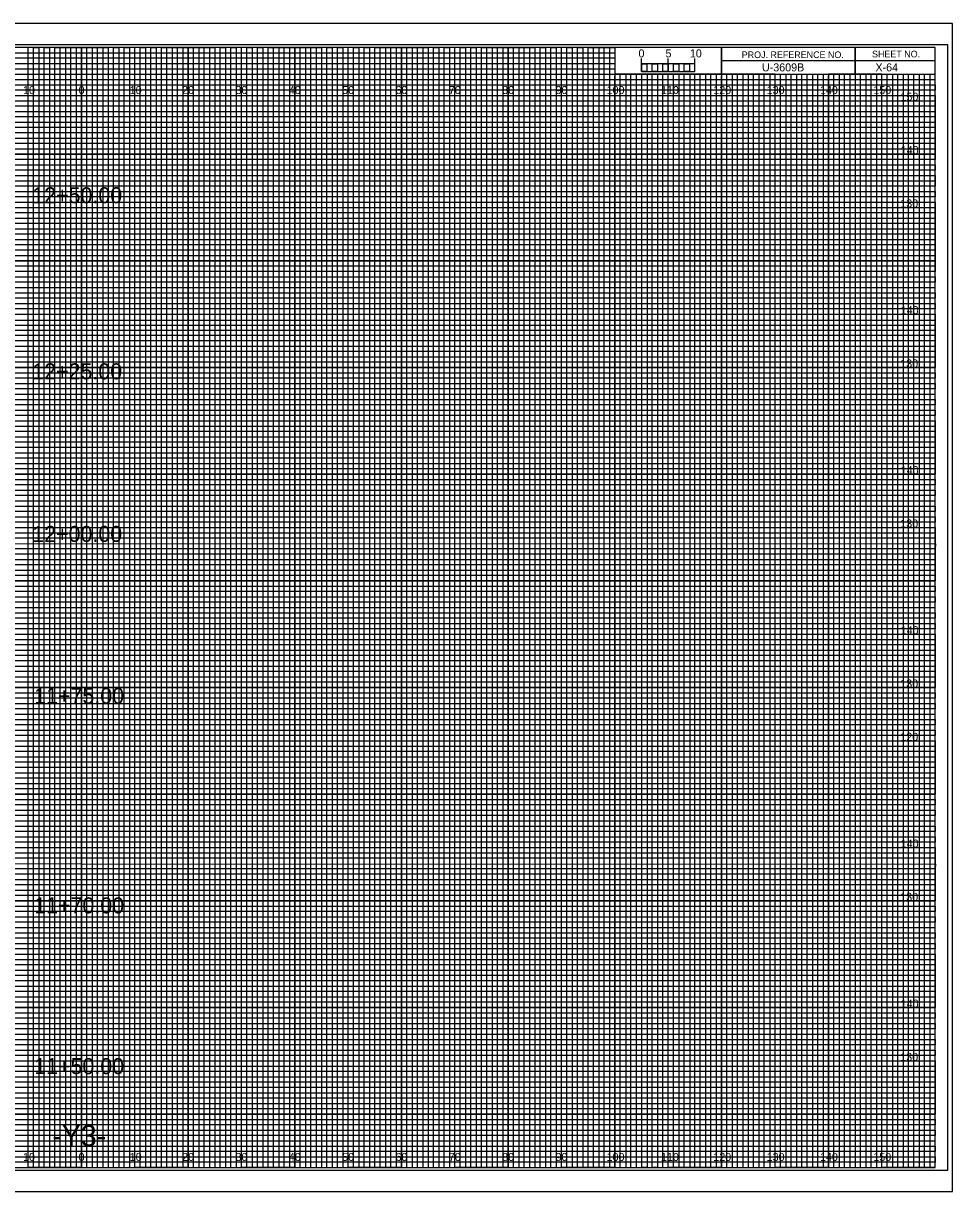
# Model space of a CAD drawing. Extents: x -13 to 323, y -5 to 215.
# Drawn here: x 149.1 to 323.3, y -4.5 to 214.5 of the extents above; entities that cross this region are included whole.
import ezdxf

# ---------------------------------------------------------------- set-up
doc = ezdxf.new("R2010")
doc.units = 0
for name, color, linetype in [('Exist CMT Pavement', 7, 'Continuous'), ('Exist Cross Section Cell', 7, 'Continuous'), ('Exist XS Center Line Elevation Label', 7, 'Continuous'), ('Exist XS Ground Line', 7, 'Continuous'), ('Prop CMT Pvmt Course 1 Wedge', 7, 'Continuous'), ('Prop CMT Pvmt Course 2', 7, 'Continuous'), ('Prop CMT Pvmt Course 2 Wedge', 7, 'Continuous'), ('Prop CMT Pvmt Course 3', 7, 'Continuous'), ('Prop CMT Pvmt Course 3 Wedge', 7, 'Continuous'), ('Prop CMT Pvmt Surface', 7, 'Continuous'), ('Prop CMT Pvmt Wedge Surface 1', 7, 'Continuous'), ('Prop CMT Pvmt Wedge Surface 2', 7, 'Continuous'), ('Prop CMT Shld Paved Course 1', 7, 'Continuous'), ('Prop CMT Shld Paved Course 2', 7, 'Continuous'), ('Prop CMT Shld Paved Course 3', 7, 'Continuous'), ('Prop CMT Subgrade Earthwork', 7, 'Continuous'), ('Scratch_Level_0', 7, 'Continuous')]:
    doc.layers.add(name, color=color, linetype=linetype)

msp = doc.modelspace()

# ---------------------------------------------------------------- linework, layer by layer
at = {"layer": 'Exist XS Center Line Elevation Label'}
for points in [[(145, 0), (155, 0), (155, 210), (165, 210), (165, 0), (175, 0), (175, 210), (185, 210), (185, 0), (195, 0), (195, 210), (205, 210), (205, 0), (215, 0), (215, 210), (225, 210), (225, 0), (235, 0), (235, 210), (245, 210), (245, 0), (255, 0), (255, 210), (259.93, 210), (260, 210), (260, 205), (264.99, 205), (264.99, 0), (275, 0), (275, 205), (285, 205), (285, 0), (295, 0), (295, 205), (305, 205), (305, 0), (315, 0), (315, 205)], [(0, 205), (275, 205)], [(0, 185), (320, 185), (320, 195), (0, 195)], [(0, 165), (320, 165), (320, 175), (0, 175)], [(0, 145), (320, 145), (320, 155), (0, 155)], [(0, 125), (320, 125), (320, 135), (0, 135)], [(0, 105), (320, 105), (320, 115), (0, 115)], [(0, 85), (320, 85), (320, 95), (0, 95)], [(0, 65), (320, 65), (320, 75), (0, 75)], [(0, 45), (320, 45), (320, 55), (0, 55)], [(0, 25), (320, 25), (320, 35), (0, 35)], [(0, 5), (320, 5), (320, 15), (0, 15)]]:
    msp.add_lwpolyline(points, dxfattribs=at)
at = {"layer": 'Exist XS Ground Line'}
for p, q in [((150, 210), (140, 210)), ((150, 0), (150, 210)), ((170, 210), (160, 210)), ((160, 210), (160, 0)), ((170, 0), (170, 210)), ((190, 210), (180, 210)), ((180, 210), (180, 0)), ((190, 0), (190, 210)), ((210, 210), (200, 210)), ((200, 210), (200, 0)), ((210, 0), (210, 210)), ((230, 210), (220, 210)), ((220, 210), (220, 0)), ((230, 0), (230, 210)), ((250, 210), (240, 210)), ((240, 210), (240, 0)), ((250, 0), (250, 210)), ((260, 210), (260, 0)), ((270, 0), (270, 205)), ((290, 205), (280, 205)), ((280, 205), (280, 0)), ((290, 0), (290, 205)), ((310, 205), (300, 205)), ((300, 205), (300, 0)), ((310, 0), (310, 205)), ((160, 0), (150, 0)), ((180, 0), (170, 0)), ((200, 0), (190, 0)), ((220, 0), (210, 0)), ((240, 0), (230, 0)), ((260, 0), (250, 0)), ((280, 0), (270, 0)), ((300, 0), (290, 0)), ((320, 0), (310, 0)), ((320, 0), (320, 0))]:
    msp.add_line(p, q, dxfattribs=at)
for points in [[(0, 200), (320, 200), (320, 190), (0, 190)], [(0, 180), (320, 180), (320, 170), (0, 170)], [(0, 160), (320, 160), (320, 150), (0, 150)], [(0, 140), (320, 140), (320, 130), (0, 130)], [(0, 120), (320, 120), (320, 110), (0, 110)], [(0, 100), (320, 100), (320, 90), (0, 90)], [(0, 80), (320, 80), (320, 70), (0, 70)], [(0, 60), (320, 60), (320, 50), (0, 50)], [(0, 40), (320, 40), (320, 30), (0, 30)], [(0, 20), (320, 20), (320, 10), (0, 10)]]:
    msp.add_lwpolyline(points, dxfattribs=at)
at = {"layer": 'Prop CMT Pvmt Course 1 Wedge'}
for p, q in [((323.3, 214.5), (-13.4, 214.5)), ((-13.4, -4.5), (323.3, -4.5))]:
    msp.add_line(p, q, dxfattribs=at)
at = {"layer": 'Prop CMT Pvmt Course 2'}
msp.add_lwpolyline([(-13.4, -4.5), (323.3, -4.5), (323.3, 214.5), (-13.4, 214.5)], close=True, dxfattribs=at)
at = {"layer": 'Prop CMT Pvmt Course 3'}
msp.add_lwpolyline([(-10.8, -0.5), (322.4, -0.5), (322.4, 210.5), (-10.8, 210.5)], close=True, dxfattribs=at)
at = {"layer": 'Prop CMT Shld Paved Course 1'}
for p, q in [((305, 210), (305, 205)), ((305, 205), (305, 210)), ((280, 207.5), (280, 205)), ((320, 207.49), (280, 207.49)), ((280, 205), (320, 205))]:
    msp.add_line(p, q, dxfattribs=at)
for points in [[(320, 210), (0, 210), (0, 0), (320, 0)], [(280, 210), (260, 210), (260, 205.03), (280, 205.03)], [(320, 210), (280, 210), (280, 205), (320, 205)]]:
    msp.add_lwpolyline(points, close=True, dxfattribs=at)
at = {"layer": 'Prop CMT Shld Paved Course 2'}
for p, q in [((267, 205), (266.01, 205)), ((266.01, 205), (266.01, 0)), ((267, 0), (267, 205)), ((269, 205), (268, 205)), ((268, 205), (268, 0)), ((269, 0), (269, 205)), ((266.01, 0), (265, 0)), ((268, 0), (267, 0))]:
    msp.add_line(p, q, dxfattribs=at)
for points in [[(150, 0), (151, 0), (151, 210), (152, 210), (152, 0)], [(152, 0), (153, 0), (153, 210), (154, 210), (154, 0)], [(155, 0), (156, 0), (156, 210), (157, 210), (157, 0)], [(157, 0), (158, 0), (158, 210), (159, 210), (159, 0)], [(160, 0), (161, 0), (161, 210), (162, 210), (162, 0)], [(162, 0), (163, 0), (163, 210), (164, 210), (164, 0)], [(165, 0), (166, 0), (166, 210), (167, 210), (167, 0)], [(167, 0), (168, 0), (168, 210), (169, 210), (169, 0)], [(170, 0), (171, 0), (171, 210), (172, 210), (172, 0)], [(172, 0), (173, 0), (173, 210), (174, 210), (174, 0)], [(175, 0), (176, 0), (176, 210), (177, 210), (177, 0)], [(177, 0), (178, 0), (178, 210), (179, 210), (179, 0)], [(180, 0), (181, 0), (181, 210), (182, 210), (182, 0)], [(182, 0), (183, 0), (183, 210), (184, 210), (184, 0)], [(185, 0), (186, 0), (186, 210), (187, 210), (187, 0)], [(187, 0), (188, 0), (188, 210), (189, 210), (189, 0)], [(190, 0), (191, 0), (191, 210), (192, 210), (192, 0)], [(192, 0), (193, 0), (193, 210), (194, 210), (194, 0)], [(195, 0), (196, 0), (196, 210), (197, 210), (197, 0)], [(197, 0), (198, 0), (198, 210), (199, 210), (199, 0)], [(200, 0), (201, 0), (201, 210), (202, 210), (202, 0)], [(202, 0), (203, 0), (203, 210), (204, 210), (204, 0)], [(205, 0), (206, 0), (206, 210), (207, 210), (207, 0)], [(207, 0), (208, 0), (208, 210), (209, 210), (209, 0)], [(210, 0), (211, 0), (211, 210), (212, 210), (212, 0)], [(212, 0), (213, 0), (213, 210), (214, 210), (214, 0)], [(215, 0), (216, 0), (216, 210), (217, 210), (217, 0)], [(217, 0), (218, 0), (218, 210), (219, 210), (219, 0)], [(220, 0), (221, 0), (221, 210), (222, 210), (222, 0)], [(222, 0), (223, 0), (223, 210), (224, 210), (224, 0)], [(225, 0), (226, 0), (226, 210), (227, 210), (227, 0)], [(227, 0), (228, 0), (228, 210), (229, 210), (229, 0)], [(230, 0), (231, 0), (231, 210), (232, 210), (232, 0)], [(232, 0), (233, 0), (233, 210), (234, 210), (234, 0)], [(235, 0), (236, 0), (236, 210), (237, 210), (237, 0)], [(237, 0), (238, 0), (238, 210), (239, 210), (239, 0)], [(240, 0), (241, 0), (241, 210), (242, 210), (242, 0)], [(242, 0), (243, 0), (243, 210), (244, 210), (244, 0)], [(245, 0), (246, 0), (246, 210), (247, 210), (247, 0)], [(247, 0), (248, 0), (248, 210), (249, 210), (249, 0)], [(250, 0), (251, 0), (251, 210), (252, 210), (252, 0)], [(252, 0), (253, 0), (253, 210), (254, 210), (254, 0)], [(255, 0), (256, 0), (256, 210), (257, 210), (257, 0)], [(257, 0), (258, 0), (258, 210), (259, 210), (259, 0)], [(260, 0), (261, 0), (261, 205), (262.02, 205), (262.02, 0)], [(262, 0), (263, 0), (263, 205), (263.99, 205), (263.99, 0)], [(270, 0), (270.98, 0), (270.98, 205), (272, 205), (272, 0)], [(272, 0), (273, 0), (273, 205), (274.05, 205), (274.05, 0)], [(275, 0), (276, 0), (276, 205), (277, 205), (277, 0)], [(277, 0), (278, 0), (278, 205), (279, 205), (279, 0)], [(280, 0), (281, 0), (281, 205), (282, 205), (282, 0)], [(282, 0), (283, 0), (283, 205), (284, 205), (284, 0)], [(285, 0), (286, 0), (286, 205), (287, 205), (287, 0)], [(287, 0), (288, 0), (288, 205), (289, 205), (289, 0)], [(290, 0), (291, 0), (291, 205), (292, 205), (292, 0)], [(292, 0), (293, 0), (293, 205), (294, 205), (294, 0)], [(295, 0), (296, 0), (296, 205), (297, 205), (297, 0)], [(297, 0), (298, 0), (298, 205), (299, 205), (299, 0)], [(300, 0), (301, 0), (301, 205), (302, 205), (302, 0)], [(302, 0), (303, 0), (303, 205), (304, 205), (304, 0)], [(305, 0), (306, 0), (306, 205), (307, 205), (307, 0)], [(307, 0), (308, 0), (308, 205), (309, 205), (309, 0)], [(310, 0), (311, 0), (311, 205), (312, 205), (312, 0)], [(312, 0), (313, 0), (313, 205), (314, 205), (314, 0)], [(315, 0), (316, 0), (316, 205), (317, 205), (317, 0)], [(317, 0), (318, 0), (318, 205), (319, 205), (319, 0)]]:
    msp.add_lwpolyline(points, dxfattribs=at)
at = {"layer": 'Prop CMT Shld Paved Course 3'}
for p, q in [((265, 205.49), (265, 207.9)), ((265, 206.9), (265, 207.9)), ((270, 205.49), (270, 207.9)), ((275, 205.49), (275, 207.9)), ((275, 206.9), (275, 207.9))]:
    msp.add_line(p, q, dxfattribs=at)
for points in [[(275, 206.9), (265, 206.9), (265, 205.49), (275, 205.49)], [(265, 206.9), (266, 206.9), (266, 205.49), (265, 205.49)], [(267, 206.9), (268, 206.9), (268, 205.49), (267, 205.49)], [(269, 206.9), (270, 206.9), (270, 205.49), (269, 205.49)], [(271, 206.9), (272, 206.9), (272, 205.49), (271, 205.49)], [(273, 206.9), (274, 206.9), (274, 205.49), (273, 205.49)]]:
    msp.add_lwpolyline(points, close=True, dxfattribs=at)
at = {"layer": 'Prop CMT Subgrade Earthwork'}
for p, q in [((150, 0), (150, 210)), ((160, 0), (160, 210)), ((170, 0), (170, 210)), ((180, 0), (180, 210)), ((190, 0), (190, 210)), ((200, 0), (200, 210)), ((210, 0), (210, 210)), ((220, 0), (220, 210)), ((230, 0), (230, 210)), ((240, 0), (240, 210)), ((250, 0), (250, 210)), ((260, 0), (260, 204.69)), ((270, 0), (270, 204.69)), ((280, 0), (280, 204.69)), ((290, 0), (290, 204.69)), ((300, 0), (300, 204.69)), ((310, 0), (310, 204.69)), ((0, 200), (320, 200)), ((0, 190), (320, 190)), ((0, 180), (320, 180)), ((0, 170), (320, 170)), ((0, 160), (320, 160)), ((0, 150), (320, 150)), ((0, 140), (320, 140)), ((0, 130), (320, 130)), ((0, 120), (320, 120)), ((0, 110), (320, 110)), ((0, 100), (320, 100)), ((0, 90), (320, 90)), ((0, 80), (320, 80)), ((0, 70), (320, 70)), ((0, 60), (320, 60)), ((0, 50), (320, 50)), ((0, 40), (320, 40)), ((0, 30), (320, 30)), ((0, 20), (320, 20)), ((0, 10), (320, 10))]:
    msp.add_line(p, q, dxfattribs=at)
at = {"layer": 'Scratch_Level_0'}
for p, q in [((0, 209), (260, 209)), ((260, 209), (260, 207.98)), ((260, 207.98), (0, 207.98)), ((0, 207), (260, 207)), ((260, 205.89), (0, 205.89)), ((260, 207), (260, 205.89)), ((0, 204), (320, 204))]:
    msp.add_line(p, q, dxfattribs=at)
for points in [[(0, 203), (270, 203), (320, 203), (320, 202), (0, 202)], [(0, 201), (320, 201), (320, 199), (0, 199)], [(0, 198), (320, 198), (320, 197), (0, 196.98)], [(0, 196), (320, 196), (320, 194), (0, 194)], [(0, 193), (320, 193), (320, 192), (0, 192)], [(0, 191), (320, 191), (320, 189), (0, 189)], [(0, 188), (320, 188), (320, 187), (0, 187)], [(0, 186), (320, 186), (320, 184), (0, 184)], [(0, 183), (320, 183), (320, 182), (0, 182)], [(0, 181), (320, 181), (320, 179), (0, 179)], [(0, 178), (320, 178), (320, 177), (0, 177)], [(0, 176), (320, 176), (320, 173.95), (320, 173), (320, 172), (0, 172)], [(0, 174), (320, 174), (320, 173), (0, 173)], [(0, 171), (320, 171), (320, 169), (0, 169.03)], [(0, 169.03), (320, 169), (320, 168), (0, 168)], [(0, 167), (320, 167), (320, 166), (0, 166)], [(0, 164), (320, 164), (320, 163), (0, 163)], [(0, 162), (320, 162), (320, 161), (0, 161)], [(-0.07, 158.89), (320, 158.89), (320, 157.88), (-0.07, 157.88)], [(0, 157), (320, 157), (320, 156), (0, 156)], [(0, 154), (320, 154), (320, 153), (0, 153)], [(0, 152), (320, 152), (320, 151), (0, 151)], [(0, 149), (320, 149), (320, 148), (0, 148)], [(0, 147), (320, 147), (320, 146), (0, 146)], [(0, 144), (320, 144), (320, 143), (0, 143)], [(0, 142), (320, 142), (320, 141), (0, 141)], [(0, 139), (320, 139), (319.99, 137.98), (0, 138)], [(0, 137), (320, 137), (320, 136), (0, 136)], [(0, 134), (320, 134), (320, 133), (0, 133)], [(0, 132), (320, 132), (320, 131), (0, 131)], [(0, 129), (320, 129), (320, 128), (0, 128)], [(0, 127), (320, 127), (320, 126), (0, 126)], [(0, 124), (320, 124), (320, 123), (0, 123)], [(0, 122), (320, 122), (320, 121), (0, 121)], [(0, 119), (320, 119), (320, 118), (0, 118)], [(0, 116.99), (320.07, 116.91), (320, 116), (0, 116)], [(0, 114), (320, 114), (320, 113), (0, 113)], [(0, 112), (320, 112), (320, 111), (0, 111)], [(0, 109), (320, 109), (320, 108), (0, 108)], [(0, 107), (320, 107), (320, 106), (0, 106)], [(0, 104), (320, 104), (320, 103), (0, 103)], [(0, 102), (320, 102), (320, 101), (0, 101)], [(0, 99), (320, 99), (320, 98), (0, 98)], [(0, 97), (320, 97), (320, 96), (0, 96)], [(0, 94), (320, 94), (320, 93), (0, 93)], [(0, 92), (320, 92), (320, 91), (0, 91)], [(0, 89), (320, 89), (320, 88), (0, 88)], [(0, 87), (320, 87), (320, 86), (0, 86)], [(0, 84), (320, 84), (320, 83), (0, 83)], [(0, 82), (320, 82), (320, 81), (0, 81)], [(0, 79), (320, 79), (319.99, 77.98), (0, 78)], [(0, 77), (320, 77), (320, 76), (0, 76)], [(0, 74), (320, 74), (320, 73), (0, 73)], [(0, 72), (320, 72), (320, 71), (0, 71)], [(0, 69), (320, 69), (320, 68), (0, 68)], [(0, 67), (320, 67), (320, 66), (0, 66)], [(0, 64), (320, 64), (320, 63), (0, 63)], [(0, 62), (320, 62), (320, 61), (0, 61)], [(0, 59), (320, 59), (320, 58), (0, 58)], [(0, 56.99), (320.07, 56.91), (320, 56), (0, 56)], [(0, 54), (320, 54), (320, 53), (0, 53)], [(0, 52), (320, 52), (320, 51), (0, 51)], [(0, 49), (320, 49), (320, 48), (0, 48)], [(0, 47), (320, 47), (320, 46), (0, 46)], [(0, 44), (320, 44), (320, 43), (0, 43)], [(0, 42), (320, 42), (320, 41), (0, 41)], [(0, 39), (320, 39), (320, 38), (0, 38)], [(0, 37), (320, 37), (320, 36), (0, 36)], [(0, 34), (320, 34), (320, 33), (0, 33)], [(0, 32), (320, 32), (320, 31), (0, 31)], [(0, 29), (320, 29), (320, 28), (0, 28)], [(0, 27), (320, 27), (320, 26), (0, 26)], [(0, 24), (320, 24), (320, 23), (0, 23)], [(0, 22), (320, 22), (320, 21), (0, 21)], [(0, 19), (320, 19), (320, 18), (0, 18)], [(0, 17), (320, 17), (320, 16), (0, 16)], [(0, 14), (320, 14), (320, 13), (0, 13)], [(0, 12), (320, 12), (320, 11), (0, 11)], [(0, 9), (320, 9), (320, 8), (0, 8)], [(0, 7), (320, 7), (320, 6), (0, 6)], [(0, 4), (320, 4), (320, 3), (0, 3)], [(0, 2), (320, 2), (320, 1), (0, 1)]]:
    msp.add_lwpolyline(points, dxfattribs=at)

# ---------------------------------------------------------------- texts
at = {"layer": 'Exist CMT Pavement'}
msp.add_text('X-64', height=1.5, dxfattribs=at).set_placement((308.83, 205.5))
at = {"layer": 'Exist Cross Section Cell'}
for s, p in [('10', (149.04, 201.25)), ('0', (159.45, 201.25)), ('0', (159.45, 201.25)), ('10', (169.04, 201.25)), ('20', (178.86, 201.25)), ('30', (188.86, 201.25)), ('40', (198.86, 201.25)), ('50', (208.86, 201.25)), ('60', (218.86, 201.25)), ('70', (228.86, 201.25)), ('80', (238.86, 201.25)), ('90', (248.86, 201.25)), ('100', (258.44, 201.25)), ('110', (268.62, 201.25)), ('120', (278.44, 201.25)), ('130', (288.44, 201.25)), ('140', (298.44, 201.25)), ('150', (308.44, 201.25)), ('10', (149.04, 1.25)), ('0', (159.45, 1.25)), ('0', (159.45, 1.25)), ('10', (169.04, 1.25)), ('20', (178.86, 1.25)), ('30', (188.86, 1.25)), ('40', (198.86, 1.25)), ('50', (208.86, 1.25)), ('60', (218.86, 1.25)), ('70', (228.86, 1.25)), ('80', (238.86, 1.25)), ('90', (248.86, 1.25)), ('100', (258.44, 1.25)), ('110', (268.62, 1.25)), ('120', (278.44, 1.25)), ('130', (288.44, 1.25)), ('140', (298.44, 1.25)), ('150', (308.44, 1.25))]:
    msp.add_text(s, height=1.5, dxfattribs=at).set_placement(p)
at = {"layer": 'Prop CMT Pvmt Course 2 Wedge'}
for s, p in [('150', (313.52, 200)), ('140', (313.57, 190)), ('130', (313.49, 180)), ('140', (313.57, 160)), ('130', (313.49, 150)), ('140', (313.57, 130)), ('130', (313.49, 120)), ('140', (313.57, 100)), ('130', (313.49, 90)), ('120', (313.5, 80)), ('140', (313.57, 60)), ('130', (313.49, 50)), ('140', (313.57, 30)), ('130', (313.49, 20))]:
    msp.add_text(s, height=1.5, dxfattribs=at).set_placement(p)
at = {"layer": 'Prop CMT Pvmt Course 3 Wedge'}
for s, p in [('12+50.00', (150.77, 180.78)), ('12+25.00', (150.77, 147.77)), ('12+00.00', (150.77, 117.29)), ('11+75.00', (151.13, 86.95)), ('11+70.00', (151.13, 47.66)), ('11+50.00', (151.13, 17.53))]:
    msp.add_text(s, height=3, dxfattribs=at).set_placement(p)
at = {"layer": 'Prop CMT Pvmt Surface'}
msp.add_text('U-3609B', height=1.5, dxfattribs=at).set_placement((287.56, 205.5))
at = {"layer": 'Prop CMT Pvmt Wedge Surface 1'}
msp.add_text('-Y3-', height=4, dxfattribs=at).set_placement((154.52, 4))
at = {"layer": 'Prop CMT Pvmt Wedge Surface 2'}
for s, p in [('5', (269.47, 208.12)), ('10', (274.04, 208.12))]:
    msp.add_text(s, height=1.5, dxfattribs=at).set_placement(p)
at = {"layer": 'Prop CMT Shld Paved Course 1'}
for s, p in [('PROJ. REFERENCE NO.', (283.77, 207.99)), ('SHEET NO.', (308.19, 208.12))]:
    msp.add_text(s, height=1.25, dxfattribs=at).set_placement(p)
at = {"layer": 'Prop CMT Shld Paved Course 3'}
msp.add_text('0', height=1.5, dxfattribs=at).set_placement((264.41, 208.12))

doc.saveas('drawing.dxf')
